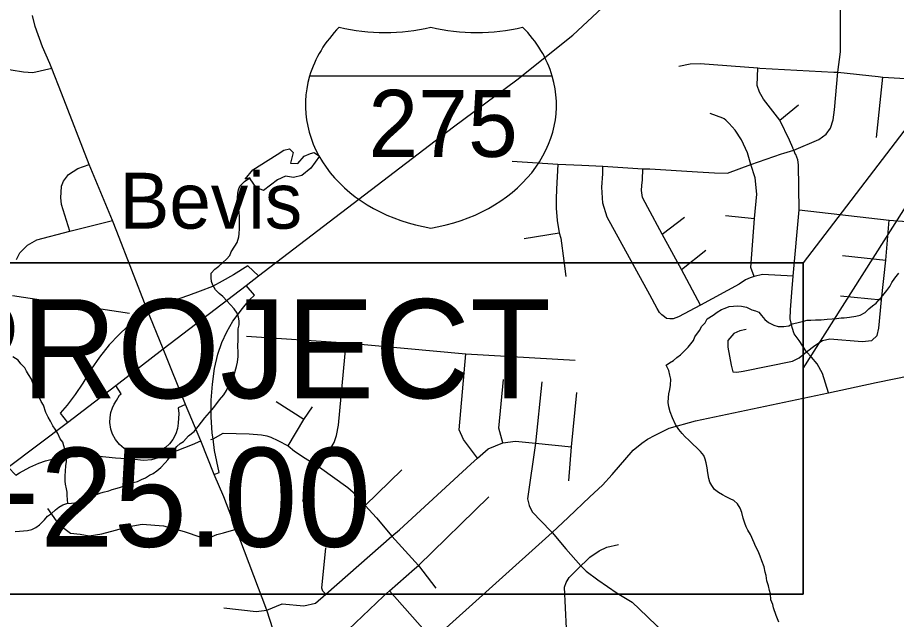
# Model space of a CAD drawing. Extents: x 0 to 69.5, y -4.5 to 22.
# Drawn here: x 3.515 to 4.758, y 17.598 to 18.449 of the extents above; entities that cross this region are included whole.
import ezdxf

# ---------------------------------------------------------------- set-up
doc = ezdxf.new("R2010")
doc.units = 0
for name, color, linetype in [('GM_X_County_Road', 7, 'Continuous'), ('GM_X_Interchange_Ramps', 7, 'Continuous'), ('GM_X_Interstate_Location', 7, 'Continuous'), ('GM_X_Interstate_Route', 7, 'Continuous'), ('GM_X_Interstate_Shield', 7, 'Continuous'), ('GM_X_Minor_Lake', 7, 'Continuous'), ('GM_X_Minor_River', 7, 'Continuous'), ('GM_X_Township_Subdivision', 7, 'Continuous'), ('GM_X_Unincorporated_Text', 7, 'Continuous'), ('GM_X_US_Route', 7, 'Continuous'), ('RD_P_Text', 7, 'Continuous'), ('SH_Masking', 7, 'Continuous')]:
    doc.layers.add(name, color=color, linetype=linetype)

msp = doc.modelspace()

# ---------------------------------------------------------------- linework, layer by layer
at = {"layer": 'GM_X_County_Road'}
for points in [[(3.5889, 18.1471), (3.5773, 18.1847), (3.5762, 18.1946), (3.5765, 18.2018), (3.5773, 18.2108), (3.5799, 18.218), (3.5872, 18.2272), (3.6002, 18.2359), (3.6162, 18.2412)], [(3.5137, 18.1072), (3.5183, 18.1165), (3.529, 18.1275), (3.5423, 18.135), (3.5889, 18.1471), (3.6491, 18.1624)], [(3.5081, 18.0561), (3.6734, 18.0314)], [(3.9249, 17.4139), (4.1024, 17.5697), (4.2708, 17.7213), (4.2935, 17.7424), (4.3241, 17.7714), (4.3423, 17.7879), (4.3557, 17.8032), (4.3855, 17.8377), (4.3976, 17.8473), (4.4059, 17.853), (4.4167, 17.859), (4.4366, 17.8686), (4.4737, 17.8792), (4.6617, 17.9188), (4.7291, 17.933), (4.8264, 17.9531), (4.956, 17.9799), (5.1816, 18.0264), (5.2178, 18.0345), (5.2322, 18.0349), (5.2647, 18.0331), (5.4907, 18.0227), (5.5592, 18.0196)]]:
    msp.add_lwpolyline(points, dxfattribs=at)
at = {"layer": 'GM_X_Interchange_Ramps'}
for points in [[(3.8558, 18.0839), (3.8408, 18.0981), (3.8205, 18.0852), (3.8043, 18.0764), (3.7905, 18.0687), (3.7732, 18.0624), (3.7567, 18.0561), (3.7336, 18.0483), (3.7062, 18.0404), (3.6977, 18.0372)], [(3.7932, 17.8031), (3.8002, 17.8062), (3.7935, 17.8369), (3.7914, 17.8536), (3.7903, 17.8618), (3.7888, 17.8849), (3.7887, 17.9084), (3.7906, 17.931), (3.7933, 17.9528), (3.7981, 17.9733), (3.8041, 17.9898), (3.8108, 18.005), (3.8195, 18.0197), (3.8329, 18.0379), (3.8428, 18.0499), (3.8499, 18.0567), (3.8382, 18.0704)], [(3.6977, 18.0372), (3.6886, 18.0297), (3.682, 18.0233), (3.6705, 18.0125), (3.658, 18.0007), (3.6447, 17.9865), (3.631, 17.9691), (3.6193, 17.9519), (3.6071, 17.9324), (3.5967, 17.9163), (3.5852, 17.9011), (3.5753, 17.8898), (3.5855, 17.8769)], [(3.7523, 17.9019), (3.7421, 17.8975), (3.743, 17.8895), (3.7423, 17.8759), (3.7411, 17.868), (3.7388, 17.8607), (3.7346, 17.8526), (3.7297, 17.8464), (3.7244, 17.8414), (3.7177, 17.8369), (3.7104, 17.8336), (3.7023, 17.8314), (3.6952, 17.8307), (3.6874, 17.8312), (3.68, 17.8328), (3.6729, 17.8356), (3.6659, 17.8397), (3.6591, 17.8456), (3.6535, 17.8526), (3.6495, 17.8601), (3.647, 17.8674), (3.6457, 17.8765), (3.6458, 17.8837), (3.647, 17.8906), (3.6492, 17.8974), (3.6518, 17.9028), (3.6551, 17.9079), (3.6592, 17.9152), (3.6614, 17.9174), (3.6539, 17.9292)], [(3.5019, 17.8134), (3.5125, 17.8021), (3.5177, 17.8053), (3.5323, 17.8134), (3.5449, 17.8194), (3.5543, 17.8225), (3.5679, 17.8259), (3.5818, 17.8276), (3.5997, 17.8288), (3.626, 17.8297), (3.6535, 17.8268), (3.6765, 17.8253), (3.6933, 17.8234), (3.705, 17.8243), (3.7177, 17.8281), (3.7299, 17.8329), (3.7623, 17.8458), (3.7741, 17.8506)]]:
    msp.add_lwpolyline(points, dxfattribs=at)
at = {"layer": 'GM_X_Interstate_Route'}
for points in [[(3.7943, 18.0368), (3.8382, 18.0704), (3.8558, 18.0839), (4.1317, 18.2944), (4.2208, 18.3608), (4.3, 18.4242), (4.3415, 18.4627), (4.3632, 18.4884), (4.3688, 18.4966)], [(3.721, 17.9807), (3.7943, 18.0368)], [(2.181, 16.4629), (2.2273, 16.5312), (2.2674, 16.589), (2.34, 16.6943), (2.3633, 16.7237), (2.4215, 16.7861), (2.4393, 16.8007), (2.4586, 16.8179), (2.4894, 16.8393), (2.7155, 16.9908), (2.8497, 17.0804), (2.9292, 17.1425), (3.0025, 17.2108), (3.0522, 17.2646), (3.1203, 17.3605), (3.2374, 17.5377), (3.2788, 17.5999), (3.3097, 17.642), (3.3406, 17.6772), (3.3886, 17.7251), (3.5019, 17.8134), (3.5855, 17.8769), (3.6539, 17.9292), (3.721, 17.9807)]]:
    msp.add_lwpolyline(points, dxfattribs=at)
at = {"layer": 'GM_X_Interstate_Shield'}
msp.add_line((4.2713, 18.3661), (3.9279, 18.3661), dxfattribs=at)
msp.add_line((4.2713, 18.3661), (3.9279, 18.3661), dxfattribs=at)
for centre, start_param, end_param in [((4.144, 18.3255), 2.47259, 2.911027), ((4.0347, 18.6054), 4.415841, 5.008937), ((4.1644, 18.6054), 4.415841, 5.008937), ((4.0552, 18.3255), 0.230566, 0.669003), ((4.144, 18.3255), 2.911027, 4.511031), ((4.0552, 18.3255), 4.913747, 6.513751)]:
    msp.add_ellipse(centre, major_axis=(0.2219, 0), ratio=0.8, start_param=start_param, end_param=end_param, dxfattribs=at)
at = {"layer": 'GM_X_Minor_Lake'}
for points in [[(3.8434, 18.2226), (3.837, 18.2207), (3.8479, 18.2338), (3.8695, 18.2475), (3.8822, 18.2556), (3.8914, 18.2615), (3.8994, 18.2636), (3.9046, 18.2585), (3.903, 18.2506), (3.9009, 18.2434), (3.9115, 18.2428), (3.9201, 18.2529), (3.9293, 18.2569), (3.9346, 18.2583), (3.9421, 18.2532), (3.9296, 18.236), (3.9169, 18.2256), (3.9051, 18.2231), (3.8941, 18.2249), (3.8826, 18.2198)], [(3.8826, 18.2198), (3.8629, 18.2046), (3.8523, 18.209), (3.8439, 18.2213), (3.8434, 18.2226)]]:
    msp.add_lwpolyline(points, dxfattribs=at)
at = {"layer": 'GM_X_Minor_River'}
for points in [[(3.8271, 17.9985), (3.8268, 18.0035), (3.827, 18.0092), (3.8282, 18.0149), (3.8283, 18.0206), (3.8273, 18.0255), (3.8255, 18.0313), (3.8215, 18.0375), (3.8163, 18.0429), (3.8111, 18.0487), (3.8055, 18.0549), (3.7999, 18.0588), (3.7947, 18.0642), (3.791, 18.0708), (3.7892, 18.0758), (3.7886, 18.0811), (3.7887, 18.0876), (3.7941, 18.0935), (3.7995, 18.0976), (3.8053, 18.1028), (3.8107, 18.1077), (3.8154, 18.1129), (3.817, 18.1178), (3.8221, 18.1261), (3.8256, 18.1309), (3.8277, 18.1389), (3.8282, 18.1434), (3.8287, 18.1507), (3.8289, 18.1632), (3.8287, 18.1685), (3.8284, 18.1731), (3.8277, 18.1781), (3.8271, 18.1834), (3.8264, 18.188), (3.8262, 18.1941), (3.8263, 18.2009), (3.8275, 18.2054), (3.8292, 18.2107), (3.8357, 18.2171), (3.8434, 18.2226)], [(4.5586, 18.0345), (4.5631, 18.0325), (4.5668, 18.0279), (4.5716, 18.0224), (4.5768, 18.0178), (4.5843, 18.0142), (4.5904, 18.0126), (4.5984, 18.0124), (4.6056, 18.0134), (4.6106, 18.016), (4.6171, 18.0177), (4.6262, 18.0198), (4.6316, 18.0212), (4.6369, 18.0215), (4.6433, 18.0218), (4.6513, 18.022), (4.6597, 18.0226), (4.6669, 18.0232), (4.673, 18.0238), (4.6795, 18.0245), (4.684, 18.0244), (4.6916, 18.0254), (4.7004, 18.0271), (4.7065, 18.0285), (4.7134, 18.0322), (4.7188, 18.0374), (4.7238, 18.0418), (4.7292, 18.0455), (4.7339, 18.0511), (4.7386, 18.0564), (4.7444, 18.0631), (4.7483, 18.0691), (4.7511, 18.0744), (4.7554, 18.0808), (4.7612, 18.0879)], [(4.5914, 17.5945), (4.5878, 17.6041), (4.5842, 17.6148), (4.5832, 17.6194), (4.5803, 17.6259), (4.5797, 17.6343), (4.5783, 17.6393), (4.5769, 17.6458), (4.5747, 17.6531), (4.5734, 17.6603), (4.5723, 17.6649), (4.5706, 17.6725), (4.5677, 17.681), (4.5652, 17.6879), (4.5623, 17.6948), (4.5587, 17.7021), (4.5565, 17.7067), (4.5514, 17.7182), (4.5477, 17.7243), (4.5455, 17.729), (4.5434, 17.7343), (4.5409, 17.7416), (4.5391, 17.7496), (4.537, 17.7557), (4.5329, 17.7615), (4.5277, 17.7666), (4.5228, 17.769), (4.5172, 17.7717), (4.5119, 17.7745), (4.5063, 17.7777), (4.5007, 17.782), (4.4966, 17.7877), (4.4941, 17.7924), (4.4923, 17.7977), (4.4909, 17.8057), (4.4903, 17.8126), (4.4889, 17.8198), (4.4875, 17.8248), (4.4853, 17.8298), (4.4809, 17.8356), (4.4749, 17.8414), (4.4705, 17.8457), (4.4641, 17.8515), (4.4589, 17.8562), (4.4548, 17.8612), (4.45, 17.867), (4.4452, 17.874), (4.4412, 17.8832), (4.438, 17.8916), (4.4362, 17.8989), (4.4348, 17.905), (4.4354, 17.9122), (4.4362, 17.9171), (4.4375, 17.9232), (4.4384, 17.9296), (4.4386, 17.938), (4.4372, 17.9437), (4.4361, 17.9502), (4.4321, 17.9579), (4.4368, 17.9612), (4.4425, 17.9642), (4.4471, 17.9686), (4.4525, 17.9723), (4.4572, 17.9768), (4.4634, 17.9831), (4.4673, 17.988), (4.4708, 17.9925), (4.4728, 17.9978), (4.4791, 18.0068), (4.4826, 18.0128), (4.4872, 18.0177), (4.4904, 18.0233), (4.4988, 18.0285), (4.5042, 18.0325), (4.5104, 18.0366), (4.5158, 18.0384), (4.5215, 18.0406), (4.5276, 18.0412), (4.5329, 18.0415), (4.5386, 18.041), (4.5458, 18.0397), (4.5533, 18.0361), (4.5586, 18.0345)], [(3.5118, 17.7226), (3.5179, 17.7233), (3.5232, 17.7236), (3.5289, 17.7242), (3.535, 17.7256), (3.5407, 17.7281), (3.5461, 17.7322), (3.5531, 17.7393), (3.5574, 17.7442), (3.5628, 17.7482), (3.5686, 17.7531), (3.5732, 17.7568), (3.579, 17.7601), (3.5847, 17.7623), (3.5912, 17.7625), (3.5957, 17.7632), (3.6007, 17.7638), (3.606, 17.7656), (3.6121, 17.7682), (3.6175, 17.7707), (3.6256, 17.7744), (3.6313, 17.7769), (3.6359, 17.7784), (3.6439, 17.7801), (3.6489, 17.7819), (3.6557, 17.7837), (3.6607, 17.7851), (3.6672, 17.7876), (3.6733, 17.7894), (3.6787, 17.7919), (3.6848, 17.7933), (3.6901, 17.7959), (3.6959, 17.7984), (3.7017, 17.8021), (3.7067, 17.8047), (3.712, 17.8084), (3.7175, 17.8132), (3.7237, 17.8196), (3.7275, 17.8241), (3.7314, 17.8293), (3.7342, 17.8353), (3.7404, 17.8428), (3.7451, 17.8469), (3.7497, 17.8499), (3.7567, 17.8577), (3.7648, 17.864), (3.7703, 17.8711), (3.7749, 17.8771), (3.78, 17.8835), (3.7866, 17.891), (3.7928, 17.8981), (3.8006, 17.9086), (3.8065, 17.9157), (3.8104, 17.922), (3.8135, 17.9281), (3.8163, 17.9326), (3.8183, 17.9379), (3.8215, 17.9439), (3.8247, 17.956), (3.826, 17.9621), (3.8269, 17.97), (3.827, 17.975), (3.8265, 17.9856), (3.827, 17.9928), (3.8271, 17.9985)], [(3.5861, 17.7623), (3.5853, 17.7737), (3.5854, 17.7782), (3.5844, 17.7828), (3.583, 17.7893), (3.5823, 17.7939), (3.5824, 17.8011), (3.583, 17.8079), (3.5835, 17.8155), (3.5844, 17.8216), (3.5841, 17.8262), (3.5827, 17.833), (3.5821, 17.8388), (3.5803, 17.8437), (3.5789, 17.8487), (3.5752, 17.8537), (3.5719, 17.861), (3.5682, 17.8672), (3.5649, 17.8722), (3.5616, 17.8787), (3.5583, 17.8841), (3.555, 17.8907), (3.5515, 17.9014), (3.5485, 17.9064), (3.5456, 17.9125), (3.5416, 17.9229), (3.5376, 17.9298), (3.5347, 17.9378), (3.5307, 17.9444), (3.5278, 17.9494), (3.5252, 17.954), (3.5196, 17.9594), (3.5159, 17.9648), (3.5084, 17.9696)]]:
    msp.add_lwpolyline(points, dxfattribs=at)
at = {"layer": 'GM_X_Township_Subdivision'}
for points in [[(4.5988, 18.2574), (4.6127, 18.2616), (4.648, 18.2766), (4.6584, 18.284), (4.6645, 18.2929), (4.6683, 18.3047), (4.6704, 18.3186), (4.6751, 18.3717), (4.6785, 18.4006), (4.6785, 18.4652)], [(3.5637, 18.377), (3.5367, 18.371), (3.5232, 18.3719), (3.488, 18.3776), (3.3929, 18.3966), (3.1812, 18.4357)], [(4.4501, 18.3805), (4.4662, 18.3837), (4.4804, 18.384), (4.5617, 18.3779), (4.5648, 18.3777)], [(4.6114, 18.2645), (4.6113, 18.2648), (4.6065, 18.2756), (4.593, 18.304), (4.57, 18.3339), (4.5642, 18.3435), (4.5609, 18.3529), (4.5617, 18.3779)], [(4.5648, 18.3777), (4.6693, 18.372)], [(4.6693, 18.372), (4.6751, 18.3717), (4.7319, 18.3656)], [(4.7294, 18.2794), (4.7387, 18.3649)], [(4.7319, 18.3656), (4.7387, 18.3649), (4.7946, 18.3616)], [(4.593, 18.304), (4.6194, 18.3258)], [(4.5565, 18.0831), (4.5521, 18.0957), (4.557, 18.1651), (4.5603, 18.1995), (4.558, 18.2226), (4.5519, 18.2414), (4.5473, 18.258), (4.5387, 18.2762), (4.5296, 18.2897), (4.5215, 18.2991), (4.5167, 18.3039), (4.5141, 18.3057), (4.5123, 18.307), (4.4943, 18.3136)], [(4.2143, 18.2459), (4.279, 18.2419), (4.313, 18.2406), (4.3427, 18.2391), (4.399, 18.2353), (4.409, 18.2351), (4.4766, 18.2308), (4.5007, 18.2296), (4.5187, 18.2293), (4.5519, 18.2414), (4.5953, 18.2563), (4.5988, 18.2574)], [(4.6154, 18.2555), (4.6153, 18.2557), (4.6127, 18.2616), (4.6114, 18.2645)], [(4.6617, 17.9188), (4.6531, 17.9459), (4.6456, 17.9597), (4.6379, 17.9692), (4.6305, 17.9764), (4.6202, 17.9924), (4.6133, 18.0019), (4.6102, 18.0111), (4.6074, 18.0232), (4.6079, 18.0361), (4.6097, 18.0602), (4.612, 18.0833), (4.6202, 18.1771), (4.6195, 18.2407), (4.6182, 18.2479), (4.6154, 18.2555)], [(4.279, 18.2419), (4.2771, 18.2064), (4.2767, 18.1927), (4.2767, 18.1798), (4.2781, 18.1623), (4.2809, 18.1447), (4.2834, 18.137), (4.2877, 18.105), (4.2901, 18.0829)], [(4.612, 18.0833), (4.5683, 18.0859), (4.5565, 18.0831), (4.5508, 18.0813), (4.5444, 18.0782), (4.5354, 18.0723), (4.4808, 18.0427), (4.4498, 18.0262), (4.4422, 18.023), (4.4372, 18.023), (4.4329, 18.0238), (4.4299, 18.0258), (4.426, 18.0288), (4.4228, 18.0321), (4.4193, 18.0377), (4.4091, 18.0571), (4.3489, 18.1668), (4.3426, 18.1865), (4.3412, 18.2093), (4.3427, 18.2281), (4.3427, 18.2391)], [(4.4808, 18.0427), (4.4539, 18.0928), (4.4267, 18.1429), (4.4064, 18.1805), (4.3986, 18.1948), (4.3975, 18.2046), (4.3979, 18.2119), (4.3985, 18.2198), (4.399, 18.2353)], [(4.5159, 18.1692), (4.557, 18.1651)], [(4.6202, 18.1771), (4.7476, 18.1625), (4.7786, 18.1601)], [(4.4267, 18.1429), (4.458, 18.1669)], [(4.5451, 18.008), (4.5363, 18.0062), (4.5278, 18.0024), (4.5194, 17.9926), (4.5196, 17.9832), (4.524, 17.9579), (4.5263, 17.9484), (4.5322, 17.948), (4.5413, 17.9493), (4.611, 17.9636), (4.6202, 17.968), (4.6305, 17.9764), (4.6426, 17.9854), (4.6533, 17.9926), (4.6634, 17.9949), (4.7093, 17.991), (4.723, 17.9926), (4.7304, 17.9998), (4.733, 18.0101), (4.7369, 18.0502), (4.7428, 18.1059), (4.7476, 18.1625)], [(4.2315, 18.1366), (4.2809, 18.1447)], [(4.4539, 18.0928), (4.4884, 18.1204)], [(4.6815, 18.1126), (4.7428, 18.1059)], [(4.6786, 18.0557), (4.7369, 18.0502)], [(3.8388, 17.9987), (3.9796, 17.9895), (4.1489, 17.9738), (4.3036, 17.965)], [(3.9182, 17.7657), (3.9233, 17.7844), (3.929, 17.7976), (3.9338, 17.8055), (3.9418, 17.8134), (3.9629, 17.8485), (3.9661, 17.8583), (3.9689, 17.8731), (3.9796, 17.9895)], [(4.1652, 17.8262), (4.1458, 17.8527), (4.1397, 17.8665), (4.1489, 17.9738)], [(4.2013, 17.8481), (4.1957, 17.8687), (4.2024, 17.9373)], [(4.2562, 17.9342), (4.2473, 17.8474), (4.2359, 17.7686), (4.2383, 17.7593), (4.2427, 17.7504), (4.2693, 17.7229)], [(4.2944, 17.794), (4.2981, 17.8425), (4.3061, 17.9189)], [(3.9199, 17.8809), (3.8807, 17.9059)], [(3.8975, 17.8437), (3.9199, 17.8809), (3.9321, 17.8986)], [(3.7881, 17.8528), (3.7914, 17.8536), (3.8059, 17.8614), (3.8426, 17.8605), (3.8598, 17.8592), (3.8675, 17.8576), (3.8734, 17.8559), (3.8833, 17.8512), (3.8975, 17.8437), (3.9067, 17.8362), (3.9215, 17.8264), (3.9418, 17.8134), (3.9822, 17.7847), (3.9936, 17.7749), (4.0066, 17.7593), (4.0226, 17.7417), (4.0442, 17.7161), (4.0818, 17.6746), (4.1066, 17.6426)], [(4.1561, 17.8178), (4.1652, 17.8262), (4.1804, 17.8396), (4.2013, 17.8481), (4.219, 17.8503), (4.2473, 17.8474), (4.2981, 17.8425)], [(3.8675, 17.6115), (3.8893, 17.6206), (3.9197, 17.6174), (3.9365, 17.6215), (3.951, 17.634), (4.0442, 17.7161), (4.0549, 17.7251), (4.1561, 17.8178)], [(4.0066, 17.7593), (4.0582, 17.8097)], [(4.0763, 17.6698), (4.0818, 17.6746), (4.1814, 17.7718)], [(3.5575, 17.7553), (3.5731, 17.7328), (3.5901, 17.7203), (3.6036, 17.7187), (3.6165, 17.7166), (3.634, 17.7193), (3.6729, 17.7299), (3.6911, 17.733), (3.7216, 17.7304), (3.7504, 17.7224), (3.774, 17.7145), (3.7846, 17.714), (3.7904, 17.7156), (3.7967, 17.7182), (3.8063, 17.7206), (3.8241, 17.7258)], [(4.2693, 17.7229), (4.2708, 17.7213), (4.2901, 17.6981), (4.3117, 17.6741), (4.3192, 17.6665), (4.3355, 17.6543), (4.363, 17.6356), (4.3842, 17.6228), (4.4055, 17.6026), (4.4193, 17.5888), (4.4209, 17.587)], [(3.951, 17.634), (3.9465, 17.6384), (3.9454, 17.6423), (3.9511, 17.6993)], [(4.319, 17.6813), (4.3243, 17.6865), (4.3374, 17.6955), (4.3484, 17.7003), (4.3646, 17.7043)], [(4.2976, 17.5167), (4.2953, 17.539), (4.2912, 17.5856), (4.2885, 17.6437), (4.2909, 17.6505), (4.2949, 17.6578), (4.3117, 17.6741), (4.319, 17.6813)], [(4.0324, 17.631), (4.0411, 17.6387), (4.0763, 17.6698)], [(4.0411, 17.6387), (4.1024, 17.5697), (4.1239, 17.545), (4.1277, 17.5359), (4.1323, 17.5252), (4.1355, 17.5024), (4.1321, 17.4618), (4.1279, 17.4175), (4.1274, 17.4093), (4.1284, 17.4029), (4.1784, 17.3083), (4.1828, 17.3009), (4.186, 17.2975), (4.191, 17.2954), (4.3329, 17.28), (4.5161, 17.2672), (4.5322, 17.2634), (4.5467, 17.2577), (4.5616, 17.2543), (4.6015, 17.2519), (4.7252, 17.2398), (4.7414, 17.2423), (4.8149, 17.2674)], [(3.9828, 17.584), (4.0324, 17.631), (4.0324, 17.631)], [(3.8067, 17.6146), (3.8525, 17.6097), (3.8675, 17.6115)]]:
    msp.add_lwpolyline(points, dxfattribs=at)
at = {"layer": 'GM_X_US_Route'}
for points in [[(3.5606, 18.3842), (3.5504, 18.4078), (3.5398, 18.4365), (3.5362, 18.452)], [(3.5771, 18.3422), (3.5637, 18.377), (3.5606, 18.3842)], [(3.6552, 18.1468), (3.6491, 18.1624), (3.6162, 18.2412), (3.5771, 18.3422)], [(3.6977, 18.0372), (3.6552, 18.1468)], [(3.721, 17.9807), (3.6977, 18.0372)], [(3.8849, 17.5574), (3.8675, 17.6115), (3.8241, 17.7258), (3.8067, 17.7717), (3.7932, 17.8031), (3.7741, 17.8506), (3.7523, 17.9019), (3.721, 17.9807)]]:
    msp.add_lwpolyline(points, dxfattribs=at)
at = {"layer": 'RD_P_Text'}
msp.add_lwpolyline([(4.6261, 17.9532), (5.1831, 18.831), (4.6261, 18.1024), (4.6261, 17.9532)], dxfattribs=at)
msp.add_lwpolyline([(2.6967, 18.1024), (4.6261, 18.1024), (4.6261, 17.6342), (2.6967, 17.6342)], close=True, dxfattribs=at)
at = {"layer": 'SH_Masking'}
msp.add_lwpolyline([(4.6261, 18.1024), (2.6967, 18.1024), (2.6967, 17.6342), (4.6261, 17.6342)], close=True, dxfattribs=at)

# ---------------------------------------------------------------- texts
at = {"layer": 'GM_X_Interstate_Location'}
for s in ['-', '.', ',']:
    msp.add_text(s, height=0.000189, dxfattribs=at).set_placement((4.0996, 18.2994))
msp.add_text('275', height=0.000189, rotation=0, dxfattribs=at).set_placement((4.0417, 18.2602))
at = {"layer": 'GM_X_Interstate_Shield'}
msp.add_text('275', height=0.0947, dxfattribs=at).set_placement((4.0111, 18.2521))
at = {"layer": 'GM_X_Unincorporated_Text'}
msp.add_text('Bevis', height=0.07898, rotation=0, dxfattribs=at).set_placement((3.6592, 18.1507))
at = {"layer": 'RD_P_Text'}
for s, p in [('BEGIN PROJECT', (2.7609, 17.911)), ('STA. 10+25.00', (2.7609, 17.701))]:
    msp.add_text(s, height=0.14, dxfattribs=at).set_placement(p)

doc.saveas('drawing.dxf')
